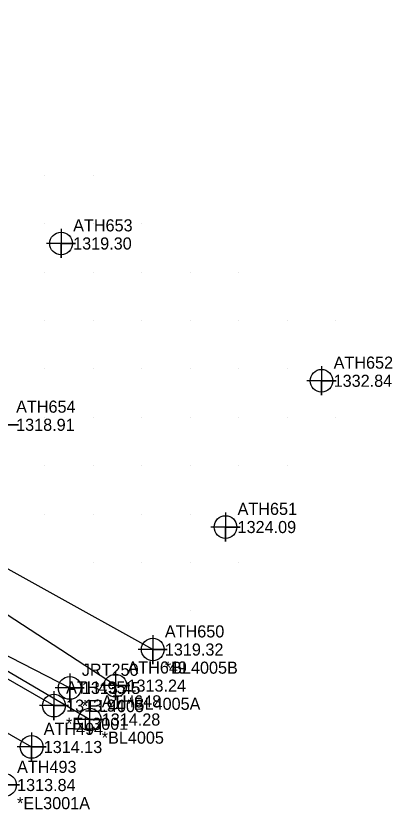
# Model space of a CAD drawing. Extents: x 1234484 to 1235382, y 695050 to 695510.
# Drawn here: x 1235304 to 1235381.7, y 695160.2 to 695323 of the extents above; entities that cross this region are included whole.
import ezdxf

# ---------------------------------------------------------------- set-up
doc = ezdxf.new("R2010")
doc.units = 0
for name, color, linetype in [('Exist DTM Breakline', 7, 'Continuous'), ('Exist DTM Breakline Cogo Comment', 7, 'Continuous'), ('Exist DTM Breakline Cogo Elevation', 7, 'Continuous'), ('Exist DTM Breakline Cogo Number', 7, 'Continuous'), ('Exist DTM Breakline Cogo Point CELL', 7, 'Continuous'), ('Exist DTM Crownline', 7, 'Continuous'), ('Exist DTM Crownline Cogo Elevation', 7, 'Continuous'), ('Exist DTM Crownline Cogo Number', 7, 'Continuous'), ('Exist DTM Crownline Cogo Point CELL', 7, 'Continuous'), ('Exist DTM QL2 LIDAR Elevation Point', 7, 'Continuous'), ('Exist DTM Regular Point CELL', 7, 'Continuous'), ('Exist DTM Regular Point Cogo Elevation', 7, 'Continuous'), ('Exist DTM Regular Point Cogo Number', 7, 'Continuous'), ('Exist Roads EOP', 7, 'Continuous'), ('Exist Roads EOP Cogo Comment', 7, 'Continuous'), ('Exist Roads EOP Cogo Elevation', 7, 'Continuous'), ('Exist Roads EOP Cogo Number', 7, 'Continuous'), ('Exist Roads EOP Cogo Point CELL', 7, 'Continuous')]:
    doc.layers.add(name, color=color, linetype=linetype)

msp = doc.modelspace()

# ---------------------------------------------------------------- linework, layer by layer
at = {"layer": 'Exist DTM Breakline'}
for points in [[(1235319.256, 695177.55), (1235278.534, 695201.47), (1235237.781, 695224.217), (1235188.481, 695250.698), (1235134.96, 695275.849), (1235082.338, 695295.901), (1235034.938, 695310.723), (1234997.435, 695322.999)], [(1235324.566, 695184.553), (1235284.54, 695210.684), (1235243.923, 695233.555), (1235196.6, 695262.635), (1235143.527, 695290.446), (1235093.587, 695315.971)], [(1235094.433, 695303.192), (1235139.249, 695284.24), (1235185.145, 695258.152), (1235235.18, 695232.365), (1235270.796, 695206.904), (1235315.147, 695184.076)], [(1235332.285, 695192.012), (1235288.571, 695216.301), (1235258.111, 695232.33), (1235245.562, 695237.206)]]:
    msp.add_lwpolyline(points, dxfattribs=at)
at = {"layer": 'Exist DTM Breakline Cogo Point CELL'}
for points in [[(1235332.285, 695195.012), (1235332.285, 695189.012), (1235332.285, 695192.012), (1235335.285, 695192.012), (1235329.285, 695192.012)], [(1235324.566, 695187.553), (1235324.566, 695181.553), (1235324.566, 695184.553), (1235327.566, 695184.553), (1235321.566, 695184.553)], [(1235315.147, 695187.076), (1235315.147, 695181.076), (1235315.147, 695184.076), (1235318.147, 695184.076), (1235312.147, 695184.076)], [(1235319.256, 695180.55), (1235319.256, 695174.55), (1235319.256, 695177.55), (1235322.256, 695177.55), (1235316.256, 695177.55)]]:
    msp.add_lwpolyline(points, dxfattribs=at)
for centre in [(1235332.285, 695192.012), (1235315.147, 695184.076), (1235324.566, 695184.553), (1235319.256, 695177.55)]:
    msp.add_circle(centre, 2.344, dxfattribs=at)
at = {"layer": 'Exist DTM Crownline'}
msp.add_lwpolyline([(1235226.8, 695217.474), (1235264.229, 695196.574), (1235307.276, 695171.87)], dxfattribs=at)
at = {"layer": 'Exist DTM Crownline Cogo Point CELL'}
msp.add_lwpolyline([(1235307.276, 695174.87), (1235307.276, 695168.87), (1235307.276, 695171.87), (1235310.276, 695171.87), (1235304.276, 695171.87)], dxfattribs=at)
msp.add_circle((1235307.276, 695171.87), 2.344, dxfattribs=at)
at = {"layer": 'Exist DTM QL2 LIDAR Elevation Point'}
for p, q in [((1235310, 695290), (1235310, 695290)), ((1235320, 695290), (1235320, 695290)), ((1235310, 695280), (1235310, 695280)), ((1235320, 695280), (1235320, 695280)), ((1235330, 695280), (1235330, 695280)), ((1235310, 695270), (1235310, 695270)), ((1235320, 695270), (1235320, 695270)), ((1235330, 695270), (1235330, 695270)), ((1235340, 695270), (1235340, 695270)), ((1235350, 695270), (1235350, 695270)), ((1235310, 695260), (1235310, 695260)), ((1235320, 695260), (1235320, 695260)), ((1235330, 695260), (1235330, 695260)), ((1235340, 695260), (1235340, 695260)), ((1235350, 695260), (1235350, 695260)), ((1235360, 695260), (1235360, 695260)), ((1235370, 695260), (1235370, 695260)), ((1235310, 695250), (1235310, 695250)), ((1235320, 695250), (1235320, 695250)), ((1235330, 695250), (1235330, 695250)), ((1235340, 695250), (1235340, 695250)), ((1235350, 695250), (1235350, 695250)), ((1235360, 695250), (1235360, 695250)), ((1235370, 695250), (1235370, 695250)), ((1235380, 695250), (1235380, 695250)), ((1235310, 695240), (1235310, 695240)), ((1235320, 695240), (1235320, 695240)), ((1235330, 695240), (1235330, 695240)), ((1235340, 695240), (1235340, 695240)), ((1235350, 695240), (1235350, 695240)), ((1235360, 695240), (1235360, 695240)), ((1235370, 695240), (1235370, 695240)), ((1235310, 695230), (1235310, 695230)), ((1235320, 695230), (1235320, 695230)), ((1235330, 695230), (1235330, 695230)), ((1235340, 695230), (1235340, 695230)), ((1235350, 695230), (1235350, 695230)), ((1235360, 695230), (1235360, 695230)), ((1235310, 695220), (1235310, 695220)), ((1235320, 695220), (1235320, 695220)), ((1235330, 695220), (1235330, 695220)), ((1235340, 695220), (1235340, 695220)), ((1235350, 695220), (1235350, 695220)), ((1235320, 695210), (1235320, 695210)), ((1235330, 695210), (1235330, 695210)), ((1235340, 695210), (1235340, 695210)), ((1235350, 695210), (1235350, 695210)), ((1235340, 695200), (1235340, 695200))]:
    msp.add_line(p, q, dxfattribs=at)
at = {"layer": 'Exist DTM Regular Point CELL'}
for points in [[(1235313.356, 695278.933), (1235313.356, 695272.933), (1235313.356, 695275.933), (1235316.356, 695275.933), (1235310.356, 695275.933)], [(1235367.127, 695250.558), (1235367.127, 695244.558), (1235367.127, 695247.558), (1235370.127, 695247.558), (1235364.127, 695247.558)], [(1235301.58, 695241.46), (1235301.58, 695235.46), (1235301.58, 695238.46), (1235304.58, 695238.46), (1235298.58, 695238.46)], [(1235347.3, 695220.333), (1235347.3, 695214.333), (1235347.3, 695217.333), (1235350.3, 695217.333), (1235344.3, 695217.333)]]:
    msp.add_lwpolyline(points, dxfattribs=at)
for centre in [(1235313.356, 695275.933), (1235367.127, 695247.558), (1235347.3, 695217.333)]:
    msp.add_circle(centre, 2.344, dxfattribs=at)
at = {"layer": 'Exist Roads EOP'}
msp.add_lwpolyline([(1235232.115, 695225.68), (1235268.895, 695205.143), (1235311.893, 695180.416)], dxfattribs=at)
at = {"layer": 'Exist Roads EOP Cogo Point CELL'}
for points in [[(1235311.893, 695183.416), (1235311.893, 695177.416), (1235311.893, 695180.416), (1235314.893, 695180.416), (1235308.893, 695180.416)], [(1235301.775, 695167.014), (1235301.775, 695161.014), (1235301.775, 695164.014), (1235304.775, 695164.014), (1235298.775, 695164.014)]]:
    msp.add_lwpolyline(points, dxfattribs=at)
for centre in [(1235311.893, 695180.416), (1235301.775, 695164.014)]:
    msp.add_circle(centre, 2.344, dxfattribs=at)

# ---------------------------------------------------------------- texts
at = {"layer": 'Exist DTM Breakline Cogo Comment'}
for s, p in [('*BL4005B', (1235334.785, 695187.012)), ('*EL4005', (1235317.647, 695179.076)), ('*BL4005A', (1235327.066, 695179.553)), ('*BL4005', (1235321.756, 695172.55))]:
    msp.add_text(s, height=2.5, dxfattribs=at).set_placement(p)
at = {"layer": 'Exist DTM Breakline Cogo Elevation'}
for s, p in [('1319.32', (1235334.785, 695190.762)), ('1313.24', (1235327.066, 695183.303)), ('1313.45', (1235317.647, 695182.826)), ('1314.28', (1235321.756, 695176.3))]:
    msp.add_text(s, height=2.5, dxfattribs=at).set_placement(p)
at = {"layer": 'Exist DTM Breakline Cogo Number'}
for s, p in [('ATH650', (1235334.785, 695194.512)), ('JRT250', (1235317.647, 695186.576)), ('ATH649', (1235327.066, 695187.053)), ('ATH648', (1235321.756, 695180.05))]:
    msp.add_text(s, height=2.5, dxfattribs=at).set_placement(p)
at = {"layer": 'Exist DTM Crownline Cogo Elevation'}
msp.add_text('1314.13', height=2.5, dxfattribs=at).set_placement((1235309.776, 695170.62))
at = {"layer": 'Exist DTM Crownline Cogo Number'}
msp.add_text('ATH494', height=2.5, dxfattribs=at).set_placement((1235309.776, 695174.37))
at = {"layer": 'Exist DTM Regular Point Cogo Elevation'}
for s, p in [('1319.30', (1235315.856, 695274.683)), ('1332.84', (1235369.627, 695246.308)), ('1318.91', (1235304.08, 695237.21)), ('1324.09', (1235349.8, 695216.083))]:
    msp.add_text(s, height=2.5, dxfattribs=at).set_placement(p)
at = {"layer": 'Exist DTM Regular Point Cogo Number'}
for s, p in [('ATH653', (1235315.856, 695278.433)), ('ATH652', (1235369.627, 695250.058)), ('ATH654', (1235304.08, 695240.96)), ('ATH651', (1235349.8, 695219.833))]:
    msp.add_text(s, height=2.5, dxfattribs=at).set_placement(p)
at = {"layer": 'Exist Roads EOP Cogo Comment'}
for s, p in [('*EL3001', (1235314.393, 695175.416)), ('*EL3001A', (1235304.275, 695159.014))]:
    msp.add_text(s, height=2.5, dxfattribs=at).set_placement(p)
at = {"layer": 'Exist Roads EOP Cogo Elevation'}
for s, p in [('1313.94', (1235314.393, 695179.166)), ('1313.84', (1235304.275, 695162.764))]:
    msp.add_text(s, height=2.5, dxfattribs=at).set_placement(p)
at = {"layer": 'Exist Roads EOP Cogo Number'}
for s, p in [('ATH495', (1235314.393, 695182.916)), ('ATH493', (1235304.275, 695166.514))]:
    msp.add_text(s, height=2.5, dxfattribs=at).set_placement(p)

doc.saveas('drawing.dxf')
